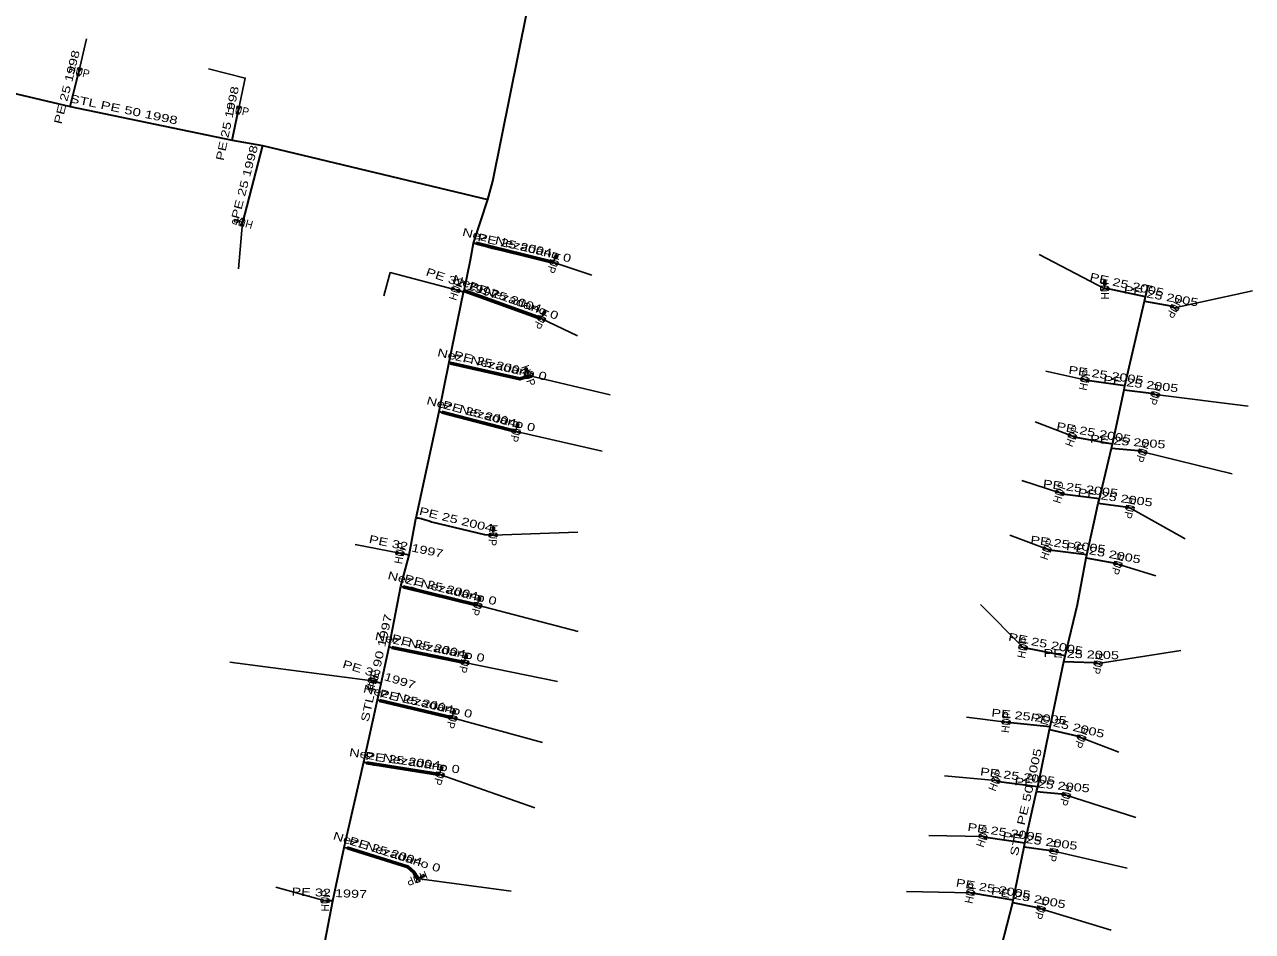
# Model space of a CAD drawing. Extents: x -737484 to -734496, y -1033882 to -1030666.
# Drawn here: x -735749 to -735595.5, y -1032051.6 to -1031938.2 of the extents above; entities that cross this region are included whole.
import ezdxf
from ezdxf.enums import TextEntityAlignment as Align

# ---------------------------------------------------------------- set-up
doc = ezdxf.new("R2010")
doc.units = 0
doc.header["$LTSCALE"] = 0.4
for name, color, linetype, lineweight in [('1', 7, 'Continuous', 13), ('18', 7, 'Continuous', 60), ('22', 7, 'Continuous', 25), ('5', 7, 'Continuous', 35), ('7', 7, 'Continuous', 35)]:
    doc.layers.add(name, color=color, linetype=linetype, lineweight=lineweight)
doc.layers.add('2', color=7, linetype='Continuous')

msp = doc.modelspace()

# ---------------------------------------------------------------- linework, layer by layer
at = {"layer": '1'}
for p, q in [((-735722.305, -1031962.727), (-735722.644, -1031962.637)), ((-735721.77, -1031962.949), (-735722.252, -1031962.819)), ((-735682.606, -1031967.461), (-735682.498, -1031967.128)), ((-735682.856, -1031967.985), (-735682.701, -1031967.509)), ((-735613.996, -1031971.248), (-735614.004, -1031970.748)), ((-735613.931, -1031970.671), (-735613.937, -1031970.321)), ((-735684.418, -1031974.976), (-735684.198, -1031974.526)), ((-735684.098, -1031974.492), (-735683.945, -1031974.177)), ((-735686.141, -1031981.529), (-735686.26, -1031981.2)), ((-735686.015, -1031982.095), (-735686.186, -1031981.625)), ((-735687.563, -1031989.077), (-735687.459, -1031988.587)), ((-735687.37, -1031988.53), (-735687.297, -1031988.187)), ((-735690.444, -1032002.038), (-735690.417, -1032001.538)), ((-735690.339, -1032001.467), (-735690.32, -1032001.118)), ((-735692.153, -1032010.235), (-735692.056, -1032009.899)), ((-735692.384, -1032010.768), (-735692.246, -1032010.287)), ((-735693.989, -1032017.934), (-735693.885, -1032017.444)), ((-735693.796, -1032017.387), (-735693.723, -1032017.044)), ((-735695.505, -1032024.868), (-735695.392, -1032024.38)), ((-735695.302, -1032024.324), (-735695.223, -1032023.983)), ((-735697.086, -1032031.95), (-735696.965, -1032031.464)), ((-735696.874, -1032031.41), (-735696.789, -1032031.07)), ((-735699.948, -1032044.935), (-735699.484, -1032044.747)), ((-735699.386, -1032044.789), (-735699.062, -1032044.658))]:
    msp.add_line(p, q, dxfattribs=at)
for points in [[(-735742.261, -1031943.585), (-735741.872, -1031943.682), (-735742.503, -1031944.555), (-735742.114, -1031944.652)], [(-735722.36, -1031948.368), (-735721.969, -1031948.451), (-735722.568, -1031949.346), (-735722.177, -1031949.429)], [(-735722.735, -1031962.69), (-735722.697, -1031962.545), (-735722.214, -1031962.674), (-735722.252, -1031962.819)], [(-735721.704, -1031963.482), (-735722.09, -1031963.379), (-735721.445, -1031962.516), (-735721.831, -1031962.413)], [(-735722.735, -1031962.69), (-735722.774, -1031962.835), (-735722.291, -1031962.964), (-735722.252, -1031962.819)], [(-735722.689, -1031962.664), (-735722.67, -1031962.591), (-735722.259, -1031962.701), (-735722.279, -1031962.774)], [(-735682.546, -1031967.033), (-735682.689, -1031966.987), (-735682.844, -1031967.463), (-735682.701, -1031967.509)], [(-735682.546, -1031967.033), (-735682.404, -1031967.08), (-735682.558, -1031967.555), (-735682.701, -1031967.509)], [(-735682.523, -1031967.081), (-735682.452, -1031967.104), (-735682.583, -1031967.508), (-735682.654, -1031967.485)], [(-735682.318, -1031967.949), (-735682.442, -1031968.329), (-735683.269, -1031967.64), (-735683.393, -1031968.02)], [(-735614.013, -1031970.248), (-735614.163, -1031970.25), (-735614.154, -1031970.75), (-735614.004, -1031970.748)], [(-735614.013, -1031970.248), (-735613.863, -1031970.245), (-735613.854, -1031970.745), (-735614.004, -1031970.748)], [(-735695.625, -1031971.39), (-735695.495, -1031971.012), (-735694.68, -1031971.715), (-735694.55, -1031971.337)], [(-735614.492, -1031971.456), (-735614.499, -1031971.056), (-735613.492, -1031971.439), (-735613.499, -1031971.039)], [(-735613.975, -1031970.285), (-735613.9, -1031970.284), (-735613.893, -1031970.709), (-735613.968, -1031970.71)], [(-735604.755, -1031973.681), (-735604.943, -1031974.034), (-735605.638, -1031973.211), (-735605.826, -1031973.564)], [(-735683.88, -1031975.015), (-735684.056, -1031975.374), (-735684.779, -1031974.577), (-735684.955, -1031974.936)], [(-735683.979, -1031974.077), (-735684.114, -1031974.011), (-735684.333, -1031974.46), (-735684.198, -1031974.526)], [(-735683.979, -1031974.077), (-735683.844, -1031974.142), (-735684.063, -1031974.592), (-735684.198, -1031974.526)], [(-735683.963, -1031974.127), (-735683.895, -1031974.16), (-735684.081, -1031974.542), (-735684.149, -1031974.509)], [(-735685.613, -1031981.736), (-735685.476, -1031982.111), (-735686.553, -1031982.078), (-735686.416, -1031982.453)], [(-735686.357, -1031981.155), (-735686.497, -1031981.206), (-735686.326, -1031981.676), (-735686.186, -1031981.625)], [(-735686.357, -1031981.155), (-735686.216, -1031981.104), (-735686.045, -1031981.573), (-735686.186, -1031981.625)], [(-735686.309, -1031981.178), (-735686.238, -1031981.152), (-735686.093, -1031981.552), (-735686.163, -1031981.577)], [(-735617.009, -1031982.702), (-735616.926, -1031982.311), (-735616.031, -1031982.91), (-735615.948, -1031982.519)], [(-735607.161, -1031984.389), (-735607.271, -1031984.774), (-735608.122, -1031984.113), (-735608.232, -1031984.498)], [(-735687.355, -1031988.098), (-735687.501, -1031988.067), (-735687.605, -1031988.556), (-735687.459, -1031988.587)], [(-735687.355, -1031988.098), (-735687.208, -1031988.13), (-735687.312, -1031988.619), (-735687.459, -1031988.587)], [(-735687.326, -1031988.143), (-735687.253, -1031988.159), (-735687.341, -1031988.575), (-735687.415, -1031988.559)], [(-735687.032, -1031988.985), (-735687.115, -1031989.376), (-735688.01, -1031988.777), (-735688.093, -1031989.168)], [(-735618.58, -1031989.671), (-735618.437, -1031989.298), (-735617.646, -1031990.029), (-735617.503, -1031989.656)], [(-735608.753, -1031991.584), (-735608.877, -1031991.964), (-735609.704, -1031991.275), (-735609.828, -1031991.655)], [(-735620.163, -1031996.766), (-735620.039, -1031996.386), (-735619.212, -1031997.075), (-735619.088, -1031996.695)], [(-735610.33, -1031998.554), (-735610.42, -1031998.944), (-735611.305, -1031998.329), (-735611.395, -1031998.719)], [(-735689.934, -1032001.864), (-735689.955, -1032002.263), (-735690.932, -1032001.812), (-735690.953, -1032002.211)], [(-735690.391, -1032001.039), (-735690.541, -1032001.031), (-735690.567, -1032001.53), (-735690.417, -1032001.538)], [(-735690.391, -1032001.039), (-735690.241, -1032001.047), (-735690.268, -1032001.546), (-735690.417, -1032001.538)], [(-735690.356, -1032001.079), (-735690.281, -1032001.083), (-735690.304, -1032001.507), (-735690.378, -1032001.503)], [(-735702.594, -1032004.397), (-735702.518, -1032004.005), (-735701.613, -1032004.588), (-735701.537, -1032004.196)], [(-735621.73, -1032003.809), (-735621.593, -1032003.434), (-735620.79, -1032004.151), (-735620.653, -1032003.776)], [(-735611.846, -1032005.607), (-735611.963, -1032005.99), (-735612.802, -1032005.315), (-735612.919, -1032005.698)], [(-735692.108, -1032009.806), (-735692.252, -1032009.765), (-735692.39, -1032010.246), (-735692.246, -1032010.287)], [(-735692.108, -1032009.806), (-735691.964, -1032009.848), (-735692.101, -1032010.328), (-735692.246, -1032010.287)], [(-735692.083, -1032009.853), (-735692.011, -1032009.874), (-735692.128, -1032010.282), (-735692.2, -1032010.262)], [(-735691.848, -1032010.713), (-735691.958, -1032011.098), (-735692.809, -1032010.437), (-735692.919, -1032010.822)], [(-735624.728, -1032016.169), (-735624.645, -1032015.778), (-735623.75, -1032016.377), (-735623.667, -1032015.986)], [(-735693.458, -1032017.842), (-735693.541, -1032018.233), (-735694.436, -1032017.634), (-735694.519, -1032018.025)], [(-735693.781, -1032016.955), (-735693.927, -1032016.924), (-735694.031, -1032017.413), (-735693.885, -1032017.444)], [(-735693.781, -1032016.955), (-735693.634, -1032016.987), (-735693.738, -1032017.476), (-735693.885, -1032017.444)], [(-735693.752, -1032017), (-735693.679, -1032017.016), (-735693.767, -1032017.432), (-735693.841, -1032017.416)], [(-735614.315, -1032017.98), (-735614.398, -1032018.371), (-735615.293, -1032017.772), (-735615.376, -1032018.163)], [(-735706.034, -1032020.289), (-735705.917, -1032019.906), (-735705.078, -1032020.581), (-735704.961, -1032020.198)], [(-735695.28, -1032023.893), (-735695.426, -1032023.859), (-735695.538, -1032024.347), (-735695.392, -1032024.38)], [(-735695.28, -1032023.893), (-735695.133, -1032023.927), (-735695.246, -1032024.414), (-735695.392, -1032024.38)], [(-735695.252, -1032023.938), (-735695.179, -1032023.955), (-735695.275, -1032024.369), (-735695.348, -1032024.353)], [(-735694.971, -1032024.788), (-735695.061, -1032025.178), (-735695.946, -1032024.563), (-735696.036, -1032024.953)], [(-735626.839, -1032025.535), (-735626.79, -1032025.138), (-735625.847, -1032025.657), (-735625.798, -1032025.26)], [(-735616.371, -1032027.336), (-735616.514, -1032027.709), (-735617.305, -1032026.978), (-735617.448, -1032027.351)], [(-735696.844, -1032030.979), (-735696.989, -1032030.943), (-735697.11, -1032031.428), (-735696.965, -1032031.464)], [(-735696.844, -1032030.979), (-735696.698, -1032031.015), (-735696.819, -1032031.501), (-735696.965, -1032031.464)], [(-735696.817, -1032031.025), (-735696.744, -1032031.043), (-735696.847, -1032031.456), (-735696.92, -1032031.437)], [(-735696.552, -1032031.876), (-735696.649, -1032032.265), (-735697.522, -1032031.634), (-735697.619, -1032032.023)], [(-735628.157, -1032032.695), (-735628.007, -1032032.324), (-735627.23, -1032033.069), (-735627.08, -1032032.698)], [(-735618.296, -1032034.472), (-735618.406, -1032034.857), (-735619.257, -1032034.196), (-735619.367, -1032034.581)], [(-735629.727, -1032039.733), (-735629.597, -1032039.355), (-735628.782, -1032040.058), (-735628.652, -1032039.68)], [(-735619.852, -1032041.401), (-735619.922, -1032041.795), (-735620.837, -1032041.228), (-735620.907, -1032041.622)], [(-735699.575, -1032045.323), (-735699.946, -1032045.473), (-735699.949, -1032044.396), (-735700.32, -1032044.546)], [(-735699.02, -1032044.56), (-735699.077, -1032044.421), (-735699.54, -1032044.608), (-735699.484, -1032044.747)], [(-735699.02, -1032044.56), (-735698.964, -1032044.699), (-735699.428, -1032044.886), (-735699.484, -1032044.747)], [(-735699.042, -1032044.608), (-735699.014, -1032044.678), (-735699.408, -1032044.837), (-735699.436, -1032044.768)], [(-735631.288, -1032046.824), (-735631.205, -1032046.433), (-735630.31, -1032047.032), (-735630.227, -1032046.641)], [(-735711.922, -1032047.897), (-735711.908, -1032047.497), (-735710.923, -1032047.932), (-735710.909, -1032047.532)], [(-735621.435, -1032048.668), (-735621.552, -1032049.051), (-735622.391, -1032048.376), (-735622.508, -1032048.759)]]:
    msp.add_lwpolyline(points, close=True, dxfattribs=at)
msp.add_lwpolyline([(-735609.137, -1031970.955), (-735609.081, -1031970.711), (-735608.106, -1031970.936), (-735608.163, -1031971.18)], dxfattribs=at)
at = {"layer": '18'}
for p, q in [((-735692.558, -1031965.567), (-735682.855, -1031967.984)), ((-735694.029, -1031971.501), (-735684.417, -1031974.975)), ((-735696.835, -1031986.684), (-735687.562, -1031989.076)), ((-735701.663, -1032008.511), (-735692.383, -1032010.768)), ((-735703.088, -1032016.068), (-735693.988, -1032017.933)), ((-735704.64, -1032022.68), (-735695.503, -1032024.87)), ((-735706.237, -1032030.492), (-735697.085, -1032031.949))]:
    msp.add_line(p, q, dxfattribs=at)
for points in [[(-735695.746, -1031980.562), (-735687.079, -1031982.514), (-735685.84, -1031982.112)], [(-735708.687, -1032041.12), (-735701.085, -1032043.492), (-735700.303, -1032044.197), (-735699.967, -1032044.91)]]:
    msp.add_lwpolyline(points, dxfattribs=at)
at = {"layer": '22'}
for p, q in [((-735742.188, -1031944.119), (-735741.26, -1031940.011)), ((-735721.768, -1031962.949), (-735722.236, -1031968.761)), ((-735613.996, -1031971.248), (-735622.21, -1031966.959)), ((-735682.856, -1031967.985), (-735678.103, -1031969.538)), ((-735605.291, -1031973.623), (-735595.547, -1031971.486)), ((-735684.418, -1031974.976), (-735679.909, -1031977.136)), ((-735686.015, -1031982.095), (-735675.82, -1031984.499)), ((-735616.479, -1031982.611), (-735621.366, -1031981.553)), ((-735607.697, -1031984.444), (-735596.062, -1031985.921)), ((-735618.042, -1031989.664), (-735622.71, -1031987.873)), ((-735687.563, -1031989.077), (-735676.824, -1031991.526)), ((-735609.291, -1031991.62), (-735598.071, -1031994.356)), ((-735619.626, -1031996.731), (-735624.383, -1031995.192)), ((-735610.863, -1031998.637), (-735603.938, -1032002.487)), ((-735690.444, -1032002.038), (-735679.836, -1032001.658)), ((-735621.192, -1032003.793), (-735625.877, -1032002.047)), ((-735702.07, -1032004.3), (-735707.663, -1032003.221)), ((-735612.383, -1032005.653), (-735607.6, -1032007.111)), ((-735692.384, -1032010.768), (-735679.807, -1032014.08)), ((-735624.198, -1032016.078), (-735629.536, -1032010.691)), ((-735614.846, -1032018.072), (-735604.498, -1032016.449)), ((-735705.5, -1032020.25), (-735723.32, -1032017.923)), ((-735693.989, -1032017.934), (-735682.383, -1032020.32)), ((-735695.504, -1032024.871), (-735684.276, -1032027.949)), ((-735626.319, -1032025.398), (-735631.28, -1032024.772)), ((-735616.91, -1032027.344), (-735612.25, -1032029.157)), ((-735697.086, -1032031.95), (-735685.233, -1032036.108)), ((-735627.619, -1032032.697), (-735634.014, -1032032.093)), ((-735618.832, -1032034.527), (-735610.121, -1032037.336)), ((-735629.19, -1032039.707), (-735635.968, -1032039.58)), ((-735620.38, -1032041.512), (-735611.192, -1032043.629)), ((-735699.948, -1032044.935), (-735688.162, -1032046.525)), ((-735711.418, -1032047.716), (-735717.579, -1032046.031)), ((-735630.758, -1032046.733), (-735638.775, -1032046.575)), ((-735621.972, -1032048.714), (-735613.201, -1032051.395))]:
    msp.add_line(p, q, dxfattribs=at)
for points in [[(-735722.269, -1031948.9), (-735721.406, -1031944.911), (-735725.98, -1031943.777)], [(-735695.088, -1031971.366), (-735703.286, -1031969.223), (-735704.074, -1031972.113)]]:
    msp.add_lwpolyline(points, dxfattribs=at)
at = {"layer": '5'}
for points in [[(-735691.099, -1031960.091), (-735690.45, -1031957.81), (-735686.19, -1031936.5), (-735684.91, -1031932.017), (-735680.31, -1031912.79), (-735676.11, -1031899.77)], [(-735782.3, -1031938.74), (-735770, -1031942.2), (-735743.28, -1031948.46), (-735723.06, -1031952.68), (-735719.26, -1031953.36), (-735691.099, -1031960.091)], [(-735716.966, -1032077.63), (-735714.831, -1032069.632), (-735714.19, -1032065.79), (-735711.61, -1032053.828), (-735710.45, -1032047.75), (-735709.025, -1032041.048), (-735706.569, -1032030.37), (-735704.884, -1032022.631), (-735704.42, -1032020.57), (-735703.406, -1032015.99), (-735701.946, -1032008.423), (-735700.92, -1032004.53), (-735700.089, -1032000), (-735700.065, -1031999.868), (-735697.165, -1031986.58), (-735695.932, -1031980.417), (-735694.12, -1031971.69), (-735694.03, -1031971.502), (-735693.24, -1031967.62), (-735692.89, -1031965.568), (-735691.099, -1031960.091)], [(-735626.899, -1032053.435), (-735625.486, -1032047.96), (-735625.43, -1032047.661), (-735624.075, -1032040.98), (-735624.004, -1032040.531), (-735622.532, -1032034.063), (-735622.373, -1032033.488), (-735620.888, -1032026.317), (-735620.814, -1032025.994), (-735619.118, -1032017.84), (-735618.968, -1032017.111), (-735617.424, -1032010.697), (-735616.314, -1032004.862), (-735616.239, -1032004.513), (-735615.253, -1032000), (-735614.823, -1031998.027), (-735614.669, -1031997.506), (-735613.145, -1031991.185), (-735613.049, -1031990.663), (-735611.56, -1031983.896), (-735611.489, -1031983.369), (-735609.054, -1031972.786), (-735608.924, -1031972.265), (-735608.594, -1031970.824)]]:
    msp.add_lwpolyline(points, dxfattribs=at)
at = {"layer": '7'}
for p, q in [((-735743.28, -1031948.46), (-735742.188, -1031944.119)), ((-735723.06, -1031952.68), (-735722.269, -1031948.899)), ((-735719.26, -1031953.36), (-735721.768, -1031962.948)), ((-735694.12, -1031971.69), (-735695.088, -1031971.364)), ((-735700.92, -1032004.53), (-735702.066, -1032004.297)), ((-735704.42, -1032020.57), (-735705.498, -1032020.244)), ((-735710.45, -1032047.75), (-735711.416, -1032047.715))]:
    msp.add_line(p, q, dxfattribs=at)
for points in [[(-735692.89, -1031965.568), (-735692.94, -1031965.556), (-735692.559, -1031965.568), (-735690.568, -1031966.192), (-735683.906, -1031967.642), (-735682.856, -1031967.985)], [(-735694.03, -1031971.502), (-735693.533, -1031971.682), (-735693.214, -1031971.797), (-735692.364, -1031972.163), (-735692.175, -1031972.249), (-735685.251, -1031974.577), (-735684.418, -1031974.976)], [(-735608.924, -1031972.265), (-735613.561, -1031971.24), (-735613.996, -1031971.248)], [(-735609.054, -1031972.786), (-735605.746, -1031973.381), (-735605.291, -1031973.623)], [(-735695.932, -1031980.417), (-735695.747, -1031980.562), (-735695.462, -1031980.543), (-735695.163, -1031980.571), (-735694.219, -1031980.759), (-735693.928, -1031980.837), (-735687.115, -1031982.488), (-735686.015, -1031982.095)], [(-735611.489, -1031983.369), (-735615.897, -1031982.737), (-735616.479, -1031982.611)], [(-735611.56, -1031983.896), (-735608.186, -1031984.305), (-735607.697, -1031984.444)], [(-735697.165, -1031986.58), (-735696.836, -1031986.685), (-735696.607, -1031986.702), (-735695.548, -1031987.042), (-735695.064, -1031987.153), (-735688.609, -1031988.849), (-735687.563, -1031989.077)], [(-735613.049, -1031990.663), (-735617.591, -1031989.837), (-735618.042, -1031989.664)], [(-735613.145, -1031991.185), (-735609.791, -1031991.453), (-735609.291, -1031991.62)], [(-735614.669, -1031997.506), (-735618.98, -1031996.94), (-735619.626, -1031996.731)], [(-735614.823, -1031998.027), (-735611.423, -1031998.508), (-735610.863, -1031998.637)], [(-735700.065, -1031999.868), (-735699.856, -1031999.858), (-735699.615, -1031999.903), (-735699.37, -1031999.976), (-735699.286, -1032000), (-735698.444, -1032000.243), (-735698.142, -1032000.367), (-735691.518, -1032001.975), (-735690.444, -1032002.038)], [(-735616.239, -1032004.513), (-735620.886, -1032003.907), (-735621.192, -1032003.793)], [(-735616.314, -1032004.862), (-735612.908, -1032005.493), (-735612.383, -1032005.653)], [(-735701.946, -1032008.423), (-735701.664, -1032008.512), (-735701.234, -1032008.546), (-735700.854, -1032008.57), (-735700.596, -1032008.578), (-735699.591, -1032008.913), (-735693.363, -1032010.486), (-735692.384, -1032010.768)], [(-735703.406, -1032015.99), (-735703.089, -1032016.069), (-735702.441, -1032016.2), (-735701.071, -1032016.356), (-735694.944, -1032017.731), (-735693.989, -1032017.934)], [(-735618.968, -1032017.111), (-735623.86, -1032016.152), (-735624.198, -1032016.078)], [(-735619.118, -1032017.84), (-735615.379, -1032017.958), (-735614.846, -1032018.072)], [(-735704.884, -1032022.631), (-735704.641, -1032022.681), (-735703.739, -1032022.995), (-735702.909, -1032023.178), (-735696.587, -1032024.628), (-735695.504, -1032024.871)], [(-735620.814, -1032025.994), (-735625.764, -1032025.468), (-735626.319, -1032025.398)], [(-735620.888, -1032026.317), (-735617.473, -1032027.125), (-735616.91, -1032027.344)], [(-735706.569, -1032030.37), (-735706.238, -1032030.493), (-735705.358, -1032030.742), (-735704.726, -1032030.816), (-735698.192, -1032031.666), (-735697.086, -1032031.95)], [(-735622.373, -1032033.488), (-735627.222, -1032032.856), (-735627.619, -1032032.697)], [(-735622.532, -1032034.063), (-735619.397, -1032034.366), (-735618.832, -1032034.527)], [(-735624.004, -1032040.531), (-735628.876, -1032039.815), (-735629.19, -1032039.707)], [(-735709.025, -1032041.048), (-735708.688, -1032041.121), (-735707.772, -1032041.276), (-735707.129, -1032041.582), (-735701.101, -1032043.428), (-735700.282, -1032044.121), (-735699.948, -1032044.935)], [(-735624.075, -1032040.98), (-735621.048, -1032041.394), (-735620.38, -1032041.512)], [(-735625.43, -1032047.661), (-735630.333, -1032046.823), (-735630.758, -1032046.733)], [(-735625.486, -1032047.96), (-735622.625, -1032048.509), (-735621.972, -1032048.714)]]:
    msp.add_lwpolyline(points, dxfattribs=at)

# ---------------------------------------------------------------- texts
at = {"layer": '18', "width": 1.35}
for rotation, p in [(346.012, (-735687.5849, -1031966.2894)), (340.129, (-735689.0525, -1031972.7671)), (347.308, (-735690.6669, -1031981.1923)), (345.536, (-735692.0734, -1031987.3952)), (346.33, (-735696.9042, -1032009.1532)), (348.418, (-735698.4369, -1032016.5105)), (346.521, (-735699.9545, -1032023.2886)), (350.954, (-735701.5816, -1032030.7264)), (342.671, (-735703.8579, -1032042.1023))]:
    msp.add_text('Nez. Nezadáno 0', height=1, rotation=rotation, dxfattribs=at).set_placement(p, align=Align.CENTER)
at = {"layer": '2', "width": 0.95}
for rotation, p in [(346, (-735742.3085, -1031944.604)), (348, (-735722.3725, -1031949.3878)), (165, (-735721.6381, -1031962.4647)), (252, (-735683.331, -1031967.83)), (71, (-735694.615, -1031971.5263)), (91, (-735613.4952, -1031971.2382)), (242, (-735605.732, -1031973.3878)), (244, (-735684.8665, -1031974.7563)), (290, (-735686.4843, -1031982.2655)), (78, (-735615.9892, -1031982.7145)), (254, (-735608.1768, -1031984.3057)), (258, (-735688.0518, -1031988.9725)), (69, (-735617.5747, -1031989.8427)), (252, (-735609.766, -1031991.465)), (72, (-735619.15, -1031996.885)), (257, (-735611.3495, -1031998.524)), (267, (-735690.9425, -1032002.0113)), (70, (-735620.7213, -1032003.9635)), (79, (-735701.5749, -1032004.3919)), (253, (-735612.8608, -1032005.5063)), (254, (-735692.8638, -1032010.6297)), (78, (-735623.7082, -1032016.1815)), (258, (-735694.4778, -1032017.8295)), (258, (-735615.3348, -1032017.9675)), (73, (-735705.0192, -1032020.3897)), (257, (-735695.9905, -1032024.758)), (83, (-735625.8223, -1032025.4584)), (249, (-735617.3763, -1032027.1643)), (256, (-735697.571, -1032031.8285)), (68, (-735627.155, -1032032.8838)), (254, (-735619.3118, -1032034.3887)), (71, (-735628.717, -1032039.8693)), (260, (-735620.8724, -1032041.4247)), (202, (-735700.1352, -1032044.471)), (78, (-735630.2682, -1032046.8365)), (88, (-735710.9157, -1032047.7319)), (253, (-735622.4498, -1032048.5673))]:
    msp.add_text('HUP', height=1, rotation=rotation, dxfattribs=at).set_placement(p, align=Align.CENTER)
at = {"layer": '5', "width": 1.4}
for s, rotation, p in [('STL PE 50 1998', 348.211, (-735736.6922, -1031949.3238)), ('STL PE 90 1997', 77.516, (-735704.5257, -1032018.7351)), ('STL PE 50 2005', 77.179, (-735623.3748, -1032035.516))]:
    msp.add_text(s, height=1, rotation=rotation, dxfattribs=at).set_placement(p, align=Align.CENTER)
at = {"layer": '7', "width": 1.35}
for s, rotation, p in [('PE 25 1998', 75.88, (-735743.2183, -1031946.167)), ('PE 25 1998', 78.184, (-735723.1533, -1031950.6869)), ('PE 25 1998', 75.341, (-735720.9975, -1031958.027)), ('PE 25 2004', 347.721, (-735687.8208, -1031966.2776)), ('PE 32 1997', 341.388, (-735694.4441, -1031971.0526)), ('PE 25 2005', 347.535, (-735611.3464, -1031971.2167)), ('PE 25 2004', 341.416, (-735689.0633, -1031972.7674)), ('PE 25 2005', 349.803, (-735607.0575, -1031972.6366)), ('PE 25 2004', 346.378, (-735690.8488, -1031981.0683)), ('PE 25 2005', 351.841, (-735613.9165, -1031982.5151)), ('PE 25 2005', 353.088, (-735609.5602, -1031983.6345)), ('PE 25 2004', 345.279, (-735692.2476, -1031987.3755)), ('PE 25 2005', 349.693, (-735615.4675, -1031989.7147)), ('PE 25 2005', 355.432, (-735611.1653, -1031990.8412)), ('PE 25 2005', 352.52, (-735617.0956, -1031996.6827)), ('PE 25 2005', 351.948, (-735612.768, -1031997.8123)), ('PE 25 2004', 346.355, (-735695.1605, -1032000.5751)), ('PE 32 1997', 348.508, (-735701.3931, -1032003.9232)), ('PE 25 2005', 352.57, (-735618.6592, -1032003.6926)), ('PE 25 2005', 349.504, (-735614.2496, -1032004.7351)), ('PE 25 2004', 345.825, (-735697.0359, -1032009.0422)), ('PE 25 2004', 347.351, (-735698.5755, -1032016.4028)), ('PE 25 2005', 348.909, (-735621.4867, -1032016.1072)), ('PE 25 2005', 358.192, (-735616.9598, -1032017.4074)), ('PE 32 1997', 343.174, (-735704.8137, -1032019.9281)), ('PE 25 2004', 347.082, (-735700.0953, -1032023.3099)), ('PE 25 2005', 353.934, (-735623.5138, -1032025.2041)), ('PE 25 2005', 346.688, (-735618.7711, -1032026.3039)), ('PE 25 2004', 352.588, (-735701.772, -1032030.6951)), ('PE 25 2005', 352.574, (-735624.9441, -1032032.6483)), ('PE 25 2005', 354.479, (-735620.6236, -1032033.7446)), ('PE 25 2005', 351.64, (-735626.5312, -1032039.6537)), ('PE 25 2005', 352.212, (-735622.1573, -1032040.7373)), ('PE 25 2004', 342.973, (-735703.9844, -1032042.0212)), ('PE 25 2005', 350.301, (-735628.0107, -1032046.7125)), ('PE 32 1997', 357.925, (-735710.9141, -1032047.2328)), ('PE 25 2005', 349.138, (-735623.6247, -1032047.8074))]:
    msp.add_text(s, height=1, rotation=rotation, dxfattribs=at).set_placement(p, align=Align.CENTER)

doc.saveas('drawing.dxf')
